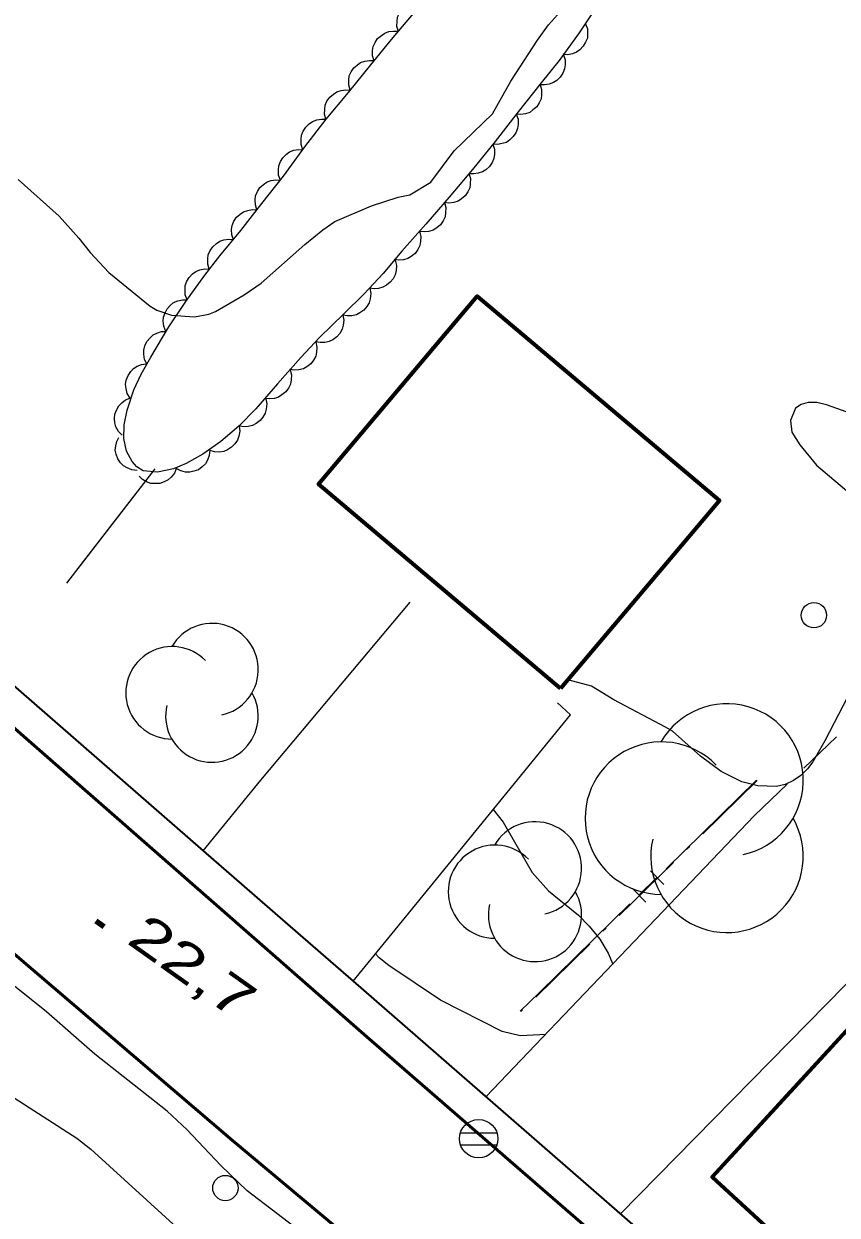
# Model space of a CAD drawing. Extents: x 356765 to 358572, y 5103174 to 5104650.
# Drawn here: x 357777.43 to 357809.57, y 5103526.75 to 5103573.84 of the extents above; entities that cross this region are included whole.
import ezdxf

# ---------------------------------------------------------------- set-up
doc = ezdxf.new("R2010")
doc.units = 0
doc.header["$LTSCALE"] = 0.6
doc.linetypes.add('DOT_DASHED', pattern=[7.7, 5, -1.2, 0.3, -1.2])
doc.linetypes.add('MEDIUM_DASHED', pattern=[4.5, 3, -1.5])
for name, color, linetype, lineweight in [('19', 7, 'Continuous', 13), ('2', 7, 'Continuous', 13), ('21', 7, 'Continuous', 53), ('22', 7, 'Continuous', 35), ('3', 7, 'Continuous', 140), ('31', 7, 'Continuous', 70), ('36', 7, 'Continuous', 13), ('37', 7, 'Continuous', 13), ('44', 7, 'Continuous', 25), ('52', 7, 'Continuous', 13)]:
    doc.layers.add(name, color=color, linetype=linetype, lineweight=lineweight)

msp = doc.modelspace()

# ---------------------------------------------------------------- linework, layer by layer
at = {"layer": '19'}
for p, q in [((357795.69, 5103531.43), (357806.3, 5103542.55)), ((357801, 5103526.8), (357813.07, 5103539.09))]:
    msp.add_line(p, q, dxfattribs=at)
for points in [[(357784.52, 5103541.16), (357786.8, 5103543.95), (357792.7, 5103550.98)], [(357790.44, 5103536.01), (357792.11, 5103538.03), (357799.03, 5103546.53), (357798.52, 5103547.01)]]:
    msp.add_lwpolyline(points, dxfattribs=at)
at = {"layer": '2'}
for points in [[(357777.21, 5103567.69), (357778.82, 5103566.24), (357779.61, 5103565.37), (357780.05, 5103564.8), (357780.79, 5103564.01), (357782.42, 5103562.68), (357782.68, 5103562.53), (357783.27, 5103562.33), (357784.17, 5103562.26), (357784.74, 5103562.37), (357785, 5103562.48), (357786.14, 5103563.13), (357786.81, 5103563.59), (357788.54, 5103565.12), (357789.24, 5103565.7), (357789.72, 5103566.03), (357791.17, 5103566.65), (357792.22, 5103567), (357792.69, 5103567.09), (357793.52, 5103567.59), (357794.44, 5103568.83), (357795.95, 5103570.29), (357796.68, 5103571.58), (357797.73, 5103573.2), (357798.17, 5103573.8), (357798.88, 5103574.59)], [(357810.75, 5103558.22), (357809.15, 5103558.79), (357808.77, 5103558.88), (357808.42, 5103558.88), (357808.15, 5103558.8), (357807.93, 5103558.65), (357807.73, 5103558.16), (357807.78, 5103557.7), (357808.1, 5103557.21), (357808.75, 5103556.4), (357810.2, 5103555.17)], [(357809.99, 5103547.25), (357809.08, 5103545.51), (357808.61, 5103544.67), (357808.4, 5103544.4), (357808.14, 5103544.13), (357807.85, 5103543.93), (357807.52, 5103543.78), (357807.17, 5103543.7), (357806.44, 5103543.72), (357805.81, 5103543.88), (357804.99, 5103544.29), (357804.17, 5103544.9), (357803.06, 5103545.88), (357802.79, 5103546.05), (357800.75, 5103547.12), (357799.86, 5103547.67), (357798.93, 5103547.91)], [(357795.98, 5103542.79), (357796.37, 5103542.29), (357797.52, 5103540.3), (357798.17, 5103539.58), (357799.35, 5103538.61), (357799.77, 5103538.18), (357800.19, 5103537.66), (357800.52, 5103537.11), (357800.7, 5103536.68)], [(357798.04, 5103533.9), (357797.82, 5103533.88), (357797.05, 5103533.84), (357796.33, 5103534.01), (357793.89, 5103535.25), (357791.85, 5103536.63), (357791.47, 5103536.93), (357791.33, 5103537.08)], [(357790.95, 5103524.13), (357786.25, 5103527.72), (357785.22, 5103528.72), (357783.89, 5103530.13), (357783.1, 5103530.86), (357780.24, 5103533.12), (357778.33, 5103534.79), (357776.13, 5103536.54)], [(357776.86, 5103531.51), (357779.53, 5103529.8), (357780.08, 5103529.36), (357783.77, 5103526.01)]]:
    msp.add_lwpolyline(points, dxfattribs=at)
at = {"layer": '21'}
for points in [[(357609.42, 5103694), (357620.2, 5103685.76), (357630.29, 5103677.74), (357638.22, 5103670.75), (357649.79, 5103660.22), (357666.81, 5103644.4), (357691.49, 5103621.57), (357705.7, 5103608.53), (357720.27, 5103594.97), (357725.87, 5103589.74), (357737.61, 5103580.01), (357753.29, 5103566.65), (357772.09, 5103550.34), (357790.98, 5103533.8), (357803.11, 5103523.29), (357815.96, 5103512.34), (357841.89, 5103502.09), (357843.77, 5103501.5), (357845.45, 5103501.88), (357846.53, 5103502.66), (357866.19, 5103521.97)], [(357727.18, 5103579.66), (357739.94, 5103568.96), (357748.99, 5103561.16), (357753.23, 5103557.51), (357769.06, 5103543.9), (357785.67, 5103529.71), (357802.28, 5103515.82), (357809.74, 5103509.32), (357813.44, 5103505.69), (357820.55, 5103498.05), (357824.21, 5103492.98), (357826.16, 5103489.76), (357827.75, 5103486.04), (357828.17, 5103484.17), (357828.46, 5103482.71), (357828.59, 5103481), (357828.35, 5103479.87), (357827.72, 5103478.51), (357826.39, 5103476.07), (357811.09, 5103450.11), (357800.54, 5103432.03), (357790.27, 5103414.46), (357780.85, 5103398.59), (357773.84, 5103386.53)]]:
    msp.add_lwpolyline(points, dxfattribs=at)
at = {"layer": '22'}
msp.add_lwpolyline([(357659.7, 5103652.78), (357665.41, 5103647.53), (357669.64, 5103643.66), (357670.81, 5103642.56), (357696.61, 5103618.59), (357708.41, 5103607.76), (357715.96, 5103600.61), (357724.74, 5103592.51), (357730.9, 5103587.2), (357739.74, 5103579.8), (357753.98, 5103567.42), (357773.1, 5103551.11), (357784.52, 5103541.16), (357787.76, 5103538.34), (357790.44, 5103536.01), (357803.72, 5103524.43), (357816.37, 5103513.51), (357815.68, 5103512.58)], dxfattribs=at)
at = {"layer": '3'}
msp.add_line((357780.27, 5103538.39), (357780.59, 5103538.16), dxfattribs=at)
at = {"layer": '31'}
for points in [[(357798.64, 5103547.57), (357789.08, 5103555.65), (357795.35, 5103563.08), (357804.92, 5103555), (357798.64, 5103547.57)], [(357813.04, 5103537.41), (357804.63, 5103528.26), (357807.43, 5103525.69), (357806.54, 5103524.73), (357808.16, 5103523.25), (357809.1, 5103524.27), (357815.15, 5103518.72), (357824.63, 5103529.04), (357823.32, 5103530.24), (357822.19, 5103529.01), (357813.04, 5103537.41)]]:
    msp.add_lwpolyline(points, close=True, dxfattribs=at)
at = {"layer": '36'}
for p, q in [((357796.12, 5103530), (357794.67, 5103530)), ((357794.67, 5103529.54), (357796.12, 5103529.54))]:
    msp.add_line(p, q, dxfattribs=at)
for centre, radius in [((357808.6538, 5103550.4671), 0.5), ((357795.4054, 5103529.7767), 0.7588), ((357785.3938, 5103527.8271), 0.5)]:
    msp.add_circle(centre, radius, dxfattribs=at)
at = {"layer": '37'}
for q in [(357779.12, 5103551.74), (357779.55, 5103552.3)]:
    msp.add_line((357782.61, 5103556.25), q, dxfattribs=at)
at = {"layer": '37', "linetype": 'DOT_DASHED', "lineweight": 25}
msp.add_line((357806.41, 5103543.93), (357797.07, 5103534.8), dxfattribs=at)
at = {"layer": '37', "lineweight": 25}
for p, q in [((357806.39, 5103543.95), (357802.81, 5103540.45)), ((357802.72, 5103539.83), (357802.2, 5103540.37)), ((357802.46, 5103540.11), (357801.74, 5103539.41)), ((357802.01, 5103539.13), (357801.48, 5103539.67)), ((357801.38, 5103539.06), (357797.81, 5103535.56)), ((357797.81, 5103535.56), (357797.05, 5103534.82))]:
    msp.add_line(p, q, dxfattribs=at)
at = {"layer": '44'}
for points in [[(357792.23, 5103573.54), (357792.17, 5103573.74), (357792.18, 5103573.95), (357792.2, 5103574.11), (357792.28, 5103574.27), (357792.39, 5103574.42), (357792.54, 5103574.54), (357792.67, 5103574.63), (357792.84, 5103574.68), (357793.02, 5103574.7), (357793.2, 5103574.68)], [(357799.63, 5103573.84), (357799.7, 5103573.65), (357799.71, 5103573.45), (357799.7, 5103573.28), (357799.63, 5103573.12), (357799.54, 5103572.96), (357799.4, 5103572.82), (357799.27, 5103572.72), (357799.11, 5103572.66), (357798.93, 5103572.62), (357798.75, 5103572.63)], [(357791.27, 5103572.38), (357791.21, 5103572.58), (357791.21, 5103572.79), (357791.24, 5103572.95), (357791.31, 5103573.11), (357791.41, 5103573.26), (357791.56, 5103573.39), (357791.69, 5103573.48), (357791.86, 5103573.54), (357792.04, 5103573.56), (357792.22, 5103573.55)], [(357790.33, 5103571.22), (357790.27, 5103571.42), (357790.27, 5103571.62), (357790.29, 5103571.79), (357790.36, 5103571.95), (357790.47, 5103572.1), (357790.61, 5103572.23), (357790.74, 5103572.32), (357790.91, 5103572.37), (357791.09, 5103572.4), (357791.27, 5103572.39)], [(357798.76, 5103572.62), (357798.82, 5103572.42), (357798.82, 5103572.22), (357798.8, 5103572.06), (357798.73, 5103571.9), (357798.63, 5103571.74), (357798.49, 5103571.61), (357798.36, 5103571.52), (357798.19, 5103571.46), (357798.01, 5103571.43), (357797.83, 5103571.44)], [(357797.83, 5103571.44), (357797.89, 5103571.25), (357797.89, 5103571.04), (357797.87, 5103570.88), (357797.8, 5103570.72), (357797.7, 5103570.56), (357797.55, 5103570.44), (357797.42, 5103570.34), (357797.25, 5103570.29), (357797.07, 5103570.26), (357796.89, 5103570.27)], [(357789.37, 5103570.07), (357789.31, 5103570.27), (357789.32, 5103570.47), (357789.34, 5103570.63), (357789.41, 5103570.79), (357789.52, 5103570.95), (357789.67, 5103571.07), (357789.8, 5103571.16), (357789.97, 5103571.21), (357790.15, 5103571.24), (357790.33, 5103571.22)], [(357788.46, 5103568.87), (357788.39, 5103569.07), (357788.39, 5103569.28), (357788.4, 5103569.44), (357788.47, 5103569.6), (357788.57, 5103569.76), (357788.71, 5103569.89), (357788.84, 5103569.99), (357789.01, 5103570.05), (357789.19, 5103570.08), (357789.37, 5103570.07)], [(357796.89, 5103570.27), (357796.96, 5103570.07), (357796.96, 5103569.87), (357796.94, 5103569.71), (357796.87, 5103569.54), (357796.77, 5103569.39), (357796.63, 5103569.26), (357796.5, 5103569.16), (357796.33, 5103569.11), (357796.15, 5103569.08), (357795.97, 5103569.09)], [(357795.97, 5103569.09), (357796.03, 5103568.89), (357796.03, 5103568.69), (357796.01, 5103568.52), (357795.94, 5103568.36), (357795.83, 5103568.21), (357795.69, 5103568.08), (357795.56, 5103567.99), (357795.39, 5103567.94), (357795.21, 5103567.91), (357795.03, 5103567.92)], [(357787.57, 5103567.67), (357787.5, 5103567.86), (357787.49, 5103568.07), (357787.51, 5103568.23), (357787.57, 5103568.4), (357787.67, 5103568.55), (357787.81, 5103568.69), (357787.93, 5103568.79), (357788.1, 5103568.85), (357788.28, 5103568.88), (357788.46, 5103568.87)], [(357786.64, 5103566.49), (357786.58, 5103566.69), (357786.57, 5103566.89), (357786.59, 5103567.05), (357786.66, 5103567.22), (357786.76, 5103567.37), (357786.9, 5103567.5), (357787.04, 5103567.6), (357787.2, 5103567.65), (357787.39, 5103567.68), (357787.57, 5103567.67)], [(357795.02, 5103567.93), (357795.08, 5103567.73), (357795.07, 5103567.52), (357795.05, 5103567.36), (357794.97, 5103567.2), (357794.87, 5103567.05), (357794.72, 5103566.93), (357794.59, 5103566.83), (357794.42, 5103566.78), (357794.23, 5103566.76), (357794.05, 5103566.78)], [(357794.05, 5103566.78), (357794.11, 5103566.58), (357794.1, 5103566.38), (357794.08, 5103566.21), (357794, 5103566.06), (357793.9, 5103565.9), (357793.75, 5103565.78), (357793.61, 5103565.69), (357793.44, 5103565.64), (357793.26, 5103565.62), (357793.08, 5103565.64)], [(357785.71, 5103565.31), (357785.65, 5103565.51), (357785.64, 5103565.72), (357785.66, 5103565.88), (357785.73, 5103566.04), (357785.84, 5103566.2), (357785.98, 5103566.32), (357786.11, 5103566.42), (357786.28, 5103566.47), (357786.46, 5103566.5), (357786.64, 5103566.49)], [(357784.76, 5103564.15), (357784.7, 5103564.35), (357784.7, 5103564.56), (357784.72, 5103564.72), (357784.79, 5103564.88), (357784.9, 5103565.03), (357785.04, 5103565.16), (357785.17, 5103565.25), (357785.34, 5103565.31), (357785.53, 5103565.33), (357785.71, 5103565.32)], [(357793.07, 5103565.65), (357793.12, 5103565.44), (357793.11, 5103565.24), (357793.08, 5103565.08), (357793, 5103564.92), (357792.89, 5103564.77), (357792.74, 5103564.65), (357792.61, 5103564.57), (357792.44, 5103564.52), (357792.25, 5103564.5), (357792.07, 5103564.53)], [(357792.11, 5103564.5), (357792.16, 5103564.29), (357792.14, 5103564.09), (357792.11, 5103563.93), (357792.03, 5103563.77), (357791.91, 5103563.63), (357791.76, 5103563.51), (357791.62, 5103563.43), (357791.45, 5103563.38), (357791.27, 5103563.37), (357791.09, 5103563.4)], [(357783.88, 5103562.94), (357783.81, 5103563.13), (357783.8, 5103563.34), (357783.81, 5103563.5), (357783.87, 5103563.67), (357783.97, 5103563.82), (357784.1, 5103563.96), (357784.23, 5103564.06), (357784.39, 5103564.12), (357784.58, 5103564.16), (357784.76, 5103564.15)], [(357791.1, 5103563.39), (357791.14, 5103563.18), (357791.12, 5103562.98), (357791.08, 5103562.82), (357790.99, 5103562.67), (357790.87, 5103562.53), (357790.71, 5103562.42), (357790.57, 5103562.34), (357790.39, 5103562.3), (357790.21, 5103562.3), (357790.03, 5103562.33)], [(357783.04, 5103561.69), (357782.96, 5103561.89), (357782.94, 5103562.09), (357782.95, 5103562.25), (357783.01, 5103562.42), (357783.1, 5103562.58), (357783.23, 5103562.72), (357783.35, 5103562.83), (357783.52, 5103562.9), (357783.7, 5103562.94), (357783.88, 5103562.94)], [(357790.03, 5103562.33), (357790.07, 5103562.13), (357790.05, 5103561.93), (357790.01, 5103561.77), (357789.92, 5103561.61), (357789.8, 5103561.47), (357789.64, 5103561.36), (357789.49, 5103561.29), (357789.32, 5103561.25), (357789.14, 5103561.25), (357788.96, 5103561.28)], [(357782.29, 5103560.4), (357782.2, 5103560.58), (357782.17, 5103560.79), (357782.17, 5103560.95), (357782.21, 5103561.12), (357782.29, 5103561.29), (357782.42, 5103561.43), (357782.54, 5103561.55), (357782.69, 5103561.62), (357782.87, 5103561.68), (357783.05, 5103561.69)], [(357788.97, 5103561.28), (357789.01, 5103561.07), (357789, 5103560.87), (357788.97, 5103560.71), (357788.88, 5103560.55), (357788.77, 5103560.41), (357788.62, 5103560.29), (357788.48, 5103560.21), (357788.3, 5103560.17), (357788.12, 5103560.15), (357787.94, 5103560.18)], [(357781.63, 5103559.05), (357781.52, 5103559.23), (357781.47, 5103559.43), (357781.45, 5103559.59), (357781.48, 5103559.76), (357781.55, 5103559.94), (357781.66, 5103560.1), (357781.76, 5103560.22), (357781.91, 5103560.31), (357782.08, 5103560.38), (357782.26, 5103560.41)], [(357787.95, 5103560.17), (357788.01, 5103559.97), (357788, 5103559.77), (357787.97, 5103559.6), (357787.89, 5103559.45), (357787.78, 5103559.3), (357787.63, 5103559.18), (357787.5, 5103559.09), (357787.33, 5103559.04), (357787.14, 5103559.02), (357786.96, 5103559.04)], [(357781.31, 5103557.58), (357781.17, 5103557.73), (357781.07, 5103557.91), (357781.02, 5103558.07), (357781.01, 5103558.24), (357781.03, 5103558.42), (357781.1, 5103558.6), (357781.18, 5103558.75), (357781.3, 5103558.87), (357781.45, 5103558.98), (357781.62, 5103559.05)], [(357786.99, 5103559.02), (357787.03, 5103558.82), (357787.01, 5103558.62), (357786.97, 5103558.45), (357786.88, 5103558.3), (357786.77, 5103558.16), (357786.61, 5103558.05), (357786.47, 5103557.97), (357786.3, 5103557.93), (357786.11, 5103557.92), (357785.93, 5103557.95)], [(357785.94, 5103557.95), (357785.96, 5103557.75), (357785.92, 5103557.55), (357785.87, 5103557.39), (357785.77, 5103557.24), (357785.64, 5103557.11), (357785.48, 5103557.01), (357785.33, 5103556.94), (357785.16, 5103556.92), (357784.97, 5103556.93), (357784.8, 5103556.98)], [(357781.91, 5103556.19), (357781.7, 5103556.21), (357781.51, 5103556.29), (357781.37, 5103556.37), (357781.25, 5103556.49), (357781.14, 5103556.65), (357781.08, 5103556.83), (357781.04, 5103556.99), (357781.06, 5103557.16), (357781.1, 5103557.34), (357781.19, 5103557.5)], [(357784.78, 5103556.99), (357784.76, 5103556.78), (357784.69, 5103556.6), (357784.61, 5103556.45), (357784.48, 5103556.33), (357784.33, 5103556.22), (357784.15, 5103556.16), (357783.99, 5103556.12), (357783.82, 5103556.13), (357783.64, 5103556.17), (357783.48, 5103556.25)], [(357783.46, 5103556.29), (357783.38, 5103556.09), (357783.25, 5103555.93), (357783.13, 5103555.82), (357782.98, 5103555.74), (357782.8, 5103555.68), (357782.61, 5103555.67), (357782.45, 5103555.68), (357782.28, 5103555.74), (357782.12, 5103555.84), (357781.99, 5103555.96)]]:
    msp.add_lwpolyline(points, dxfattribs=at)
at = {"layer": '44', "linetype": 'DOT_DASHED'}
msp.add_lwpolyline([(357800.11, 5103574.59), (357799.37, 5103573.49), (357798.58, 5103572.4), (357797.88, 5103571.51), (357796.96, 5103570.36), (357796.05, 5103569.19), (357795.16, 5103568.09), (357794.24, 5103567), (357793.32, 5103565.92), (357792.37, 5103564.86), (357791.63, 5103563.98), (357790.87, 5103563.16), (357790.08, 5103562.38), (357789.12, 5103561.44), (357788.38, 5103560.65), (357787.46, 5103559.61), (357786.6, 5103558.63), (357785.92, 5103557.94), (357785.22, 5103557.34), (357784.51, 5103556.84), (357783.84, 5103556.46), (357783.34, 5103556.26), (357782.71, 5103556.12), (357782.14, 5103556.18), (357781.9, 5103556.33), (357781.71, 5103556.55), (357781.49, 5103556.95), (357781.38, 5103557.45), (357781.4, 5103558), (357781.52, 5103558.57), (357781.78, 5103559.38), (357782.07, 5103560), (357782.45, 5103560.67), (357783.16, 5103561.87), (357783.83, 5103562.87), (357784.58, 5103563.91), (357785.18, 5103564.67), (357786, 5103565.68), (357786.84, 5103566.74), (357787.69, 5103567.83), (357788.54, 5103568.98), (357789.38, 5103570.08), (357790.26, 5103571.13), (357791.14, 5103572.22), (357792.02, 5103573.3), (357792.91, 5103574.34)], dxfattribs=at)
at = {"layer": '44'}
for centre, radius, start, end in [((357784.8644, 5103548.3166), 1.8301, 282.26917, 149.72626), ((357783.2905, 5103547.4016), 1.8301, 44.11537, 269.80396), ((357784.8644, 5103546.4865), 1.8301, 166.93686, 29.62122), ((357805.2191, 5103543.9557), 3.0146, 282.26917, 149.72626), ((357802.6266, 5103542.4485), 3.0146, 44.11537, 269.80396), ((357797.6297, 5103540.4633), 1.8428, 282.26917, 149.72626), ((357805.2191, 5103540.9412), 3.0146, 166.93686, 29.62122), ((357796.0449, 5103539.5418), 1.8428, 44.11537, 269.80396), ((357797.6297, 5103538.6204), 1.8428, 166.93686, 29.62122)]:
    msp.add_arc(centre, radius, start, end, dxfattribs=at)
at = {"layer": '52', "linetype": 'MEDIUM_DASHED'}
msp.add_lwpolyline([(357806.3, 5103542.55), (357818.56, 5103554.3), (357838.63, 5103534.69), (357824.59, 5103521.22)], dxfattribs=at)

# ---------------------------------------------------------------- texts
at = {"layer": '3', "width": 1.4}
msp.add_text('22,7   ', height=1.5, rotation=324.619, dxfattribs=at).set_placement((357781.44, 5103537.54))

doc.saveas('drawing.dxf')
